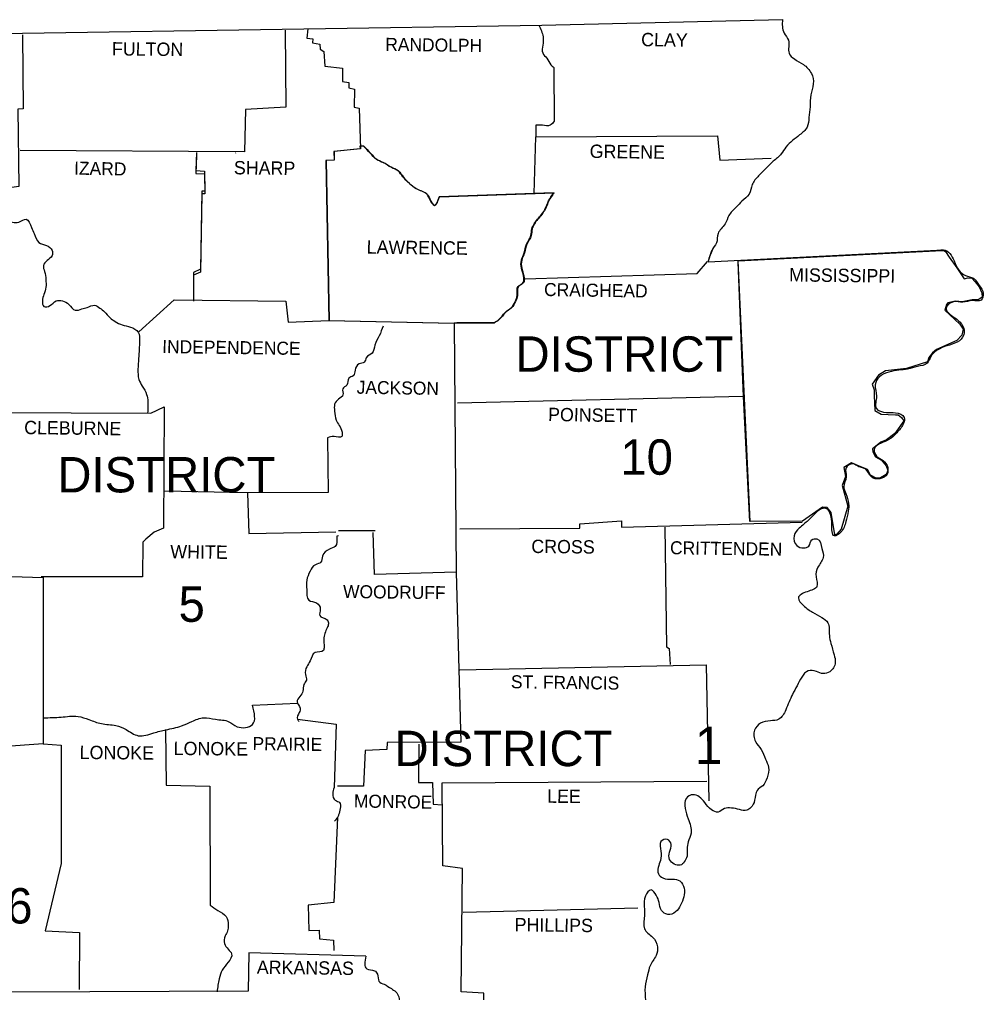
# Model space of a CAD drawing. Extents: x -42408 to 34530, y -43140 to 20491.
# Drawn here: x 3107 to 4663, y -8719 to -7149 of the extents above; entities that cross this region are included whole.
import ezdxf

# ---------------------------------------------------------------- set-up
doc = ezdxf.new("R2010")
doc.units = 0
for name, color, linetype in [('1', 7, 'Continuous'), ('2', 7, 'Continuous'), ('3', 7, 'Continuous'), ('S_MISC_BOUNDARY', 7, 'Continuous')]:
    doc.layers.add(name, color=color, linetype=linetype)

msp = doc.modelspace()

# ---------------------------------------------------------------- linework, layer by layer
at = {"layer": '1'}
for p, q in [((3940.7, -7320.1), (3940.7, -7338.7)), ((3662.3, -7353.7), (3656.7, -7353.9)), ((3968.7, -7429.3), (3784.5, -7435.8)), ((3937.2, -7430.8), (3938.1, -7429.9)), ((3777, -7449.3), (3781.8, -7444.6)), ((4218.6, -7540.4), (4224.6, -7521.9)), ((4220.1, -7534.4), (4226.1, -7519.9)), ((4267, -7538.6), (4596.4, -7522.4)), ((4596.4, -7522.4), (4599.2, -7522.2)), ((4599.2, -7522.2), (4601.6, -7523.9)), ((4601.6, -7523.9), (4607.9, -7533)), ((4607.9, -7533), (4619.9, -7550.3)), ((4286.6, -7959.5), (4267, -7538.6)), ((4619.9, -7550.3), (4632, -7567.6)), ((4632, -7567.6), (4638, -7566)), ((4638, -7566), (4644.1, -7567)), ((4644.1, -7567), (4649.6, -7572.7)), ((4649.6, -7572.7), (4655.9, -7581)), ((4655.9, -7581), (4660.6, -7590.3)), ((4660.7, -7597.3), (4654.5, -7601.7)), ((4660.6, -7590.3), (4660.7, -7597.3)), ((4603.2, -7609.4), (4600.8, -7618.6)), ((4605.3, -7606.6), (4603.2, -7609.4)), ((4618.1, -7603.8), (4605.3, -7606.6)), ((4628.7, -7605), (4618.1, -7603.8)), ((4644.8, -7601.8), (4628.7, -7605)), ((4654.5, -7601.7), (4644.8, -7601.8)), ((4600.8, -7618.6), (4624.9, -7641)), ((4624.9, -7641), (4630.4, -7649.2)), ((4628.3, -7658.9), (4620.1, -7667.1)), ((4630.4, -7649.2), (4628.3, -7658.9)), ((4620.1, -7667.1), (4587.4, -7681.6)), ((4581, -7687), (4575.1, -7694.7)), ((4587.4, -7681.6), (4581, -7687)), ((4572.6, -7702), (4538.6, -7712.7)), ((4575.1, -7694.7), (4572.6, -7702)), ((4493.6, -7723.5), (4483.6, -7737.7)), ((4505, -7716.3), (4493.6, -7723.5)), ((4538.6, -7712.7), (4505, -7716.3)), ((4483.6, -7737.7), (4486.7, -7746.8)), ((4486.7, -7746.8), (4486.7, -7756.5)), ((4486.7, -7756.5), (4487.6, -7780.3)), ((4487.6, -7780.3), (4497.7, -7786.4)), ((4497.7, -7786.4), (4509.4, -7786.7)), ((4509.4, -7786.7), (4521.2, -7787.1)), ((4534.3, -7796.8), (4519.9, -7817.2)), ((4521.2, -7787.1), (4525.4, -7787.2)), ((4525.4, -7787.2), (4530.9, -7791.4)), ((4530.9, -7791.4), (4534.3, -7796.8)), ((4519.9, -7817.2), (4506.4, -7827.5)), ((4497.6, -7831.2), (4484.1, -7842.1)), ((4506.4, -7827.5), (4497.6, -7831.2)), ((4484.1, -7842.1), (4484.6, -7847.2)), ((4484.6, -7847.2), (4488.7, -7855)), ((4449.8, -7864.7), (4437.9, -7872.3)), ((4461.2, -7869.4), (4449.8, -7864.7)), ((4488.7, -7855), (4498.6, -7860.5)), ((4498.6, -7860.5), (4506.2, -7869.7)), ((4437.9, -7872.3), (4438.5, -7878.2)), ((4438.5, -7878.2), (4440.3, -7886.7)), ((4476, -7875.4), (4461.2, -7869.4)), ((4480.9, -7884.4), (4476, -7875.4)), ((4508.8, -7876.9), (4505.8, -7883.3)), ((4506.2, -7869.7), (4508.8, -7876.9)), ((4440.3, -7886.7), (4435.2, -7901.2)), ((4489.8, -7889.4), (4480.9, -7884.4)), ((4496.9, -7889.1), (4489.8, -7889.4)), ((4505.8, -7883.3), (4496.9, -7889.1)), ((4435.2, -7901.2), (4444.1, -7934.5)), ((4403.4, -7936.1), (4371.2, -7958.9)), ((4410.6, -7936.6), (4403.4, -7936.1)), ((4417.2, -7944.7), (4410.6, -7936.6)), ((4444.1, -7934.5), (4433.6, -7971.9)), ((4371.2, -7958.9), (4286.6, -7959.5)), ((4423.4, -7981), (4417.2, -7944.7)), ((3621.8, -7974), (3681.4, -7974)), ((4433.6, -7971.9), (4426.2, -7980)), ((4426.2, -7980), (4423.4, -7981))]:
    msp.add_line(p, q, dxfattribs=at)
for points in [[(1592.1, -7172.4), (2401.7, -7172.9), (3112.1, -7171.4), (3950.2, -7158.4), (4338.7, -7149.4)], [(3536.2, -7166.9), (3537.2, -7291.1), (3472.1, -7294.6), (3470.1, -7362.7), (3108.1, -7360.7)], [(3572.6, -7164.3), (3570.7, -7179.4), (3580.7, -7180.9), (3580.2, -7187), (3591.7, -7189.5), (3592.7, -7197.5), (3598.3, -7201), (3599.8, -7225), (3628.3, -7228), (3628.3, -7249.5), (3638.8, -7251), (3638.8, -7259.6), (3647.8, -7262.1), (3647.3, -7291.1), (3655.3, -7292.6), (3657.3, -7358.2), (3614.8, -7362.2), (3615.3, -7376.2), (3602.3, -7376.7), (3606.8, -7635.1), (3808.5, -7639.6), (3812, -8041.1), (3680.4, -8044.6), (3677.9, -7977)], [(3112.1, -7174.4), (3113.1, -7293.6), (3104.6, -7294.1), (3106.1, -7418.8), (3071.1, -7423.8), (3074.1, -7457.3), (3086.1, -7472.8), (3085.1, -7512.4), (3017, -7514.9), (3014.5, -7576), (2952.4, -7578), (2949.4, -7652.1), (2952.9, -7658.1), (2954.4, -7776.2), (3061.5, -7783.3), (3060, -8047.1), (3145.2, -8049.6), (3145.2, -8318), (3078.1, -8323), (3073.1, -8382), (2960.4, -8382.6)], [(3969.8, -7227), (3970.3, -7313.6)], [(3938.1, -7430.4), (3940.7, -7338.7), (3940.7, -7338.7), (4233.6, -7337.2), (4237.6, -7376.2), (4320.2, -7373.2)], [(3656.7, -7353.9), (3656.8, -7358.2), (3614.3, -7362.2), (3614.8, -7376.2), (3601.8, -7376.7), (3606.3, -7635.1), (3808, -7639.6)], [(3393, -7364.2), (3392, -7393.2), (3406, -7394.2), (3406.5, -7426.3), (3401.5, -7426.3), (3399.5, -7552.4), (3388, -7557.4), (3388, -7599.5)], [(3393, -7368.7), (3392, -7397.7), (3406, -7398.7), (3406.5, -7430.8), (3401.5, -7430.8), (3399.5, -7556.9), (3388, -7562), (3388, -7604)], [(3455.6, -7365.2), (3456.1, -7364.7)], [(3785, -7435.8), (3970.8, -7429.3)], [(3968.8, -7429.8), (3968.7, -7429.3)], [(4218.6, -7540.4), (4598.6, -7520.9)], [(3923.2, -7568), (4201.1, -7559), (4217.6, -7539.9)], [(4266.6, -7540.9), (4275.2, -7757.7), (4285.2, -7959.5)], [(3299.9, -7653.1), (3356.9, -7601.5), (3537.2, -7604), (3540.7, -7637.6), (3606.3, -7635.1)], [(3808, -7639.6), (3812.5, -7638.6), (3873.6, -7638.6)], [(3874.1, -7638.6), (3813, -7638.6), (3808.5, -7639.6)], [(4275.2, -7757.7), (3814, -7768.2)], [(3061.5, -7783.3), (3318.9, -7784.8), (3340.9, -7774.2), (3339.4, -7970), (3324.4, -7976.5), (3310.9, -7988), (3306.4, -7992.5), (3305.9, -8048.6), (3142.1, -8048.6)], [(3604.3, -7824.3), (3605.3, -7912.4), (3475.1, -7912.9), (3341.4, -7910.4)], [(3475.1, -7912.9), (3477.1, -7978.5), (3617.8, -7976)], [(3818, -7971), (4011.3, -7970), (4011.8, -7963), (4078.9, -7958), (4078.9, -7968.5), (4370.3, -7960.5)], [(4149, -7968.5), (4151.5, -8161.3), (4156, -8164.3), (4157.5, -8190.3)], [(3621.8, -7982.5), (3619.3, -7983)], [(3812, -8041.1), (3819.6, -8315.5), (3700.4, -8316), (3699.9, -8327), (3665.3, -8329), (3662.3, -8386.1), (3620.3, -8386.1)], [(3818, -8198.8), (4215.6, -8190.8)], [(4215.6, -8190.8), (4219.6, -8410.1)], [(3483.1, -8255.9), (3555.7, -8252.4)], [(3555.7, -8278.4), (3618.3, -8286.4), (3614.8, -8388.6)], [(3342.9, -8294.9), (3343.9, -8384.6), (3414.5, -8386.1), (3415, -8578.3)], [(3145.2, -8318), (3174.2, -8320), (3174.7, -8511.2), (3148.7, -8619.9), (3204.2, -8622.4), (3203.7, -8714.5)], [(3751.5, -8318.5), (3751, -8380.5), (3774, -8380.5), (3775, -8415.1), (3789.5, -8416.6)], [(3818, -8824.6), (3857.1, -8822.1), (3856.6, -8720.5), (3820.1, -8718), (3822.1, -8519.2), (3790.5, -8514.7), (3789.5, -8381), (4216.6, -8378)], [(3620.3, -8436.6), (3614.3, -8573.8), (3573.2, -8578.3), (3574.2, -8618.9), (3590.7, -8618.4), (3591.2, -8632.4), (3613.8, -8634.9), (3614.3, -8651.4)], [(3823.1, -8589.8), (4105.4, -8582.8)], [(3666.3, -8660.4), (3477.1, -8655.4), (3476.1, -8717), (3093.1, -8718.5)]]:
    msp.add_lwpolyline(points, dxfattribs=at)
for points in [[(3945.4, -7158.5), (3952.2, -7177.4), (3951.7, -7191), (3951.7, -7203.5), (3958.2, -7212), (3964.7, -7222.5), (3969.8, -7227)], [(4338.7, -7149.4), (4341.2, -7171.4), (4348.3, -7183), (4349.3, -7204), (4357.8, -7213), (4372.3, -7222), (4385.3, -7236.5), (4388.3, -7253.5), (4384.3, -7271.1), (4383.3, -7290.6), (4381.3, -7307.6), (4378.3, -7323.1), (4366.3, -7335.7), (4354.8, -7344.7), (4344.3, -7355.2), (4336.7, -7366.2), (4323.7, -7378.2), (4310.7, -7390.7), (4300.2, -7401.7), (4289.7, -7415.8), (4284.7, -7431.3), (4273.2, -7442.3), (4264.1, -7452.3), (4252.1, -7465.8), (4246.1, -7479.3), (4234.6, -7494.9), (4232.1, -7509.9), (4224.6, -7521.9), (4224.1, -7523.9)], [(3970.3, -7313.6), (3963.7, -7320.1), (3951.2, -7320.1), (3940.7, -7320.1)], [(3784.5, -7435.8), (3776.5, -7449.3), (3769, -7438.8), (3763.5, -7430.3), (3747, -7422.3), (3736.4, -7413.8), (3725.9, -7403.2), (3718.4, -7393.7), (3706.9, -7387.7), (3693.9, -7380.2), (3682.9, -7374.7), (3673.4, -7365.2), (3662.3, -7353.7)], [(3662.8, -7353.7), (3673.9, -7365.2), (3683.4, -7374.7), (3694.4, -7380.2), (3707.4, -7387.7), (3718.9, -7393.7), (3726.4, -7403.2), (3736.9, -7413.8), (3747.5, -7422.3), (3764, -7430.3), (3769.5, -7438.8), (3777, -7449.3), (3785, -7435.8)], [(3873.6, -7638.6), (3881.1, -7633.6), (3891.1, -7622), (3900.7, -7614.5), (3907.2, -7604.5), (3910.2, -7594.5), (3912.2, -7580), (3919.7, -7574.5), (3920.7, -7563), (3917.2, -7550.4), (3917.2, -7537.9), (3921.7, -7525.9), (3925.7, -7511.9), (3932.7, -7497.9), (3934.2, -7487.4), (3943.2, -7471.8), (3955.2, -7455.8), (3961.2, -7441.8), (3968.8, -7429.8)], [(3969.3, -7429.8), (3961.7, -7441.8), (3955.7, -7455.8), (3943.7, -7471.8), (3934.7, -7487.4), (3933.2, -7497.9), (3926.2, -7511.9), (3922.2, -7525.9), (3917.7, -7537.9), (3917.7, -7550.4), (3921.2, -7563), (3920.2, -7574.5), (3912.7, -7580), (3910.7, -7594.5), (3907.7, -7604.5), (3901.2, -7614.5), (3891.6, -7622), (3881.6, -7633.6), (3874.1, -7638.6)], [(3086.1, -7472.8), (3106.1, -7476.3), (3118.1, -7471.8), (3126.6, -7484.9), (3131.1, -7494.9), (3138.6, -7509.4), (3150.7, -7513.9), (3159.7, -7521.9), (3159.7, -7530.4), (3151.7, -7538.4), (3145.7, -7546.4), (3147.7, -7555.9), (3149.7, -7569), (3149.7, -7581.5), (3146.7, -7593), (3144.2, -7603.5), (3146.7, -7612.5), (3156.2, -7611), (3166.2, -7603.5), (3176.7, -7603.5), (3186.7, -7609), (3197.2, -7618.5), (3207.7, -7616.5), (3216.2, -7614), (3228.3, -7610.5), (3236.8, -7615), (3244.3, -7621), (3253.3, -7630.5), (3261.8, -7636.6), (3272.8, -7642.1), (3286.3, -7645.6), (3298.9, -7654.1), (3300.9, -7668.6), (3300.4, -7681.1), (3299.4, -7696.6), (3298.4, -7713.7), (3299.9, -7730.2), (3305.4, -7741.2), (3312.4, -7754.2), (3314.4, -7766.2), (3313.9, -7785.3)], [(4593.1, -7521.4), (4598.6, -7520.9), (4615.6, -7538.9), (4623.1, -7553.9), (4634.1, -7562.5), (4646.7, -7567), (4656.2, -7578.5), (4662.7, -7591), (4659.2, -7602), (4645.2, -7603), (4629.6, -7605.5), (4614.6, -7605), (4602.6, -7615), (4613.6, -7628.5), (4628.1, -7641.1), (4632.1, -7654.6), (4624.1, -7667.6), (4608.1, -7674.6), (4592.6, -7680.6), (4578.6, -7692.6), (4572.1, -7704.1), (4556.5, -7709.2), (4540.5, -7713.7), (4526.5, -7715.2), (4510.5, -7718.2), (4495, -7725.7), (4488.4, -7738.7), (4490.4, -7757.2), (4489.9, -7776.7), (4506.5, -7783.3), (4521, -7783.8), (4535, -7791.3), (4533.5, -7802.3), (4523, -7816.3), (4510.5, -7827.3), (4498, -7832.8), (4486.4, -7843.3), (4490.4, -7853.8), (4501, -7860.9), (4508.5, -7872.4), (4507.5, -7882.9), (4495.5, -7890.4), (4482.4, -7887.4), (4472.9, -7874.9), (4461.9, -7870.9), (4452.4, -7866.4), (4441.4, -7872.9), (4441.4, -7887.4), (4437.4, -7902.9), (4440.9, -7914.4), (4445.4, -7930.4), (4444.9, -7942.5), (4440.9, -7959.5), (4432.4, -7977), (4422.4, -7982.5), (4418.3, -7963.5), (4416.3, -7948), (4410.3, -7939), (4402.3, -7938.5), (4391.8, -7946), (4380.3, -7957.5), (4365.8, -7970), (4357.3, -7982.5), (4361.8, -7998), (4372.8, -8002), (4381.3, -7999), (4385.8, -7989), (4394.3, -7987.5), (4402.3, -8003)], [(3693.9, -7644.1), (3687.9, -7659.6), (3680.9, -7674.6), (3676.4, -7687.6), (3666.8, -7695.1), (3663.8, -7702.1), (3655.3, -7705.1), (3648.8, -7715.2), (3645.8, -7724.2), (3638.8, -7728.2), (3635.3, -7739.2), (3628.8, -7745.2), (3629.3, -7755.2), (3621.8, -7762.2), (3615.8, -7770.2), (3615.8, -7781.2), (3618.3, -7795.8), (3623.3, -7804.3), (3627.8, -7815.3), (3627.3, -7822.3), (3614.8, -7822.3), (3604.3, -7824.3)], [(3619.3, -7983), (3616.8, -7999.5), (3607.3, -8004), (3596.3, -8015.1), (3593.7, -8025.1), (3584.7, -8029.1), (3576.2, -8039.6), (3570.7, -8054.1), (3570.7, -8069.1), (3574.2, -8086.2), (3586.7, -8090.7), (3592.7, -8100.7), (3591.7, -8111.2), (3603.8, -8118.2), (3605.8, -8124.2), (3603.8, -8130.7), (3598.3, -8149.2), (3598.8, -8161.8), (3597.8, -8167.3), (3584.2, -8170.8), (3576.2, -8184.3), (3570.7, -8193.8), (3568.7, -8206.3), (3570.2, -8215.3), (3566.2, -8222.3), (3564.7, -8232.9), (3559.7, -8241.9), (3555.2, -8250.4), (3560.2, -8260.4), (3558.7, -8267.4), (3555.7, -8278.4), (3558.2, -8281.9)], [(4402.3, -8003), (4404.3, -8017.6), (4395.8, -8033.1), (4392.8, -8048.6), (4394.3, -8064.1), (4378.3, -8072.6), (4364.3, -8082.7), (4372.3, -8094.7), (4387.3, -8105.7), (4402.3, -8114.2), (4411.8, -8122.7), (4414.3, -8143.2), (4416.8, -8156.2), (4421.9, -8174.3), (4423.9, -8186.8), (4414.8, -8201.8), (4404.3, -8204.8), (4393.3, -8201.3), (4380.3, -8200.3), (4369.8, -8210.3), (4362.3, -8224.3), (4354.8, -8238.4), (4349.3, -8250.4), (4343.8, -8263.4), (4332.7, -8278.4), (4319.2, -8280.9), (4303.2, -8284.9), (4293.7, -8295.9), (4295.2, -8314.5), (4304.2, -8327), (4311.2, -8342.5), (4316.2, -8356), (4313.7, -8373), (4306.7, -8385.6), (4297.7, -8393.1), (4293.7, -8409.1), (4287.2, -8421.1), (4281.2, -8425.1), (4269.2, -8424.1), (4256.1, -8421.6), (4245.1, -8422.6), (4234.6, -8428.1), (4224.1, -8424.6), (4213.1, -8412.6), (4204.1, -8403.6), (4194.1, -8400.1), (4183.5, -8405.6), (4181.5, -8422.1), (4186.5, -8439.1), (4191, -8462.2), (4186.5, -8476.2), (4185, -8499.2)], [(3146.2, -8275.9), (3174.2, -8274.9), (3201.7, -8273.9), (3219.3, -8278.9), (3239.3, -8285.4), (3262.8, -8288.4), (3279.3, -8294.9), (3298.9, -8304.9), (3323.9, -8300.4), (3343.4, -8295.4), (3368.9, -8288.9), (3385.5, -8281.9), (3404.5, -8275.9), (3423.5, -8278.4), (3445.1, -8282.4), (3458.6, -8290.4), (3483.1, -8286.9), (3483.1, -8255.9)], [(3614.8, -8388.6), (3612.8, -8398.6), (3616.8, -8409.1), (3623.8, -8412.6), (3624.8, -8422.6), (3622.3, -8432.6), (3620.3, -8436.6), (3615.8, -8442.6)], [(4185, -8499.2), (4173.5, -8513.7), (4156.5, -8504.7), (4156.5, -8492.7), (4159, -8480.2), (4153, -8472.2), (4142.5, -8475.7), (4142.5, -8491.2), (4141.5, -8506.2), (4138.5, -8527.7), (4145.5, -8534.3), (4161.5, -8536.3), (4173, -8539.3), (4180, -8550.8), (4179.5, -8564.8), (4174, -8578.3), (4166, -8589.3), (4153.5, -8593.3), (4143.5, -8586.8), (4139.5, -8573.8), (4135, -8562.3), (4126.5, -8553.8), (4117.4, -8563.3), (4115.4, -8580.8), (4115.9, -8595.8), (4115.9, -8616.4), (4129, -8629.9), (4137, -8645.4), (4134.5, -8659.4), (4125, -8675.9), (4121, -8690.5), (4116.9, -8710), (4117.4, -8731.5), (4113.9, -8752.5), (4106.9, -8766.6), (4093.9, -8778.1), (4085.4, -8785.6), (4078.4, -8793.1), (4074.9, -8808.1), (4072.4, -8818.6), (4062.9, -8831.1), (4055.4, -8832.2), (4049.4, -8827.1), (4047.4, -8818.6), (4047.4, -8810.1), (4043.3, -8801.6), (4030.8, -8798.1), (4020.8, -8798.6), (4016.3, -8805.6), (4022.8, -8825.1), (4025.3, -8837.7), (4021.8, -8854.7), (4023.8, -8856.7), (4005.8, -8866.2), (3991.3, -8867.7), (3979.3, -8871.2), (3967.7, -8878.7), (3962.2, -8889.7), (3954.2, -8898.7), (3947.2, -8907.3), (3937.7, -8911.3), (3927.2, -8909.3), (3913.2, -8907.8), (3905.2, -8917.8), (3907.7, -8932.3), (3917.2, -8940.8), (3931.2, -8944.8), (3945.7, -8943.8), (3959.7, -8942.3), (3972.8, -8949.3), (3970.3, -8962.8), (3957.7, -8969.3), (3939.2, -8971.3), (3924.2, -8969.8), (3906.2, -8973.8), (3897.2, -8985.4), (3902.2, -9002.9), (3921.7, -9009.9), (3930.7, -9026.4), (3931.2, -9041.9), (3924.7, -9062.5), (3915.7, -9072), (3898.2, -9076), (3884.6, -9078.5), (3882.6, -9101.5), (3876.6, -9113), (3866.1, -9116.5), (3851.1, -9109), (3842.1, -9105.5), (3831.1, -9100.5), (3817, -9092), (3806.5, -9093.5), (3809.5, -9115.5), (3810.5, -9116.5), (3822.6, -9133.1), (3834.6, -9146.1), (3840.1, -9161.6)], [(3415, -8578.3), (3427.5, -8586.8), (3440.5, -8596.8), (3444.1, -8610.4), (3443, -8619.9), (3439, -8627.9), (3438, -8640.4), (3444.1, -8649.4), (3449.6, -8656.9), (3444.1, -8670.4), (3434.5, -8683), (3429.5, -8697), (3426, -8718)], [(3666.3, -8660.4), (3667.8, -8680.9), (3679.9, -8684), (3684.9, -8689.5), (3687.4, -8701), (3695.9, -8706), (3707.4, -8713), (3714.4, -8718), (3719.4, -8726), (3722.4, -8739), (3730.4, -8747.5), (3741.4, -8751.5), (3749.5, -8761.1), (3754.5, -8774.6), (3762.5, -8780.6), (3770.5, -8791.1), (3774.5, -8795.6), (3781.5, -8807.6), (3788.5, -8813.6), (3793.5, -8817.1), (3801.5, -8819.6), (3811.5, -8826.1), (3818, -8836.2), (3818, -8843.7), (3815.5, -8855.2), (3813.5, -8867.2), (3812.5, -8880.7), (3811.5, -8892.7), (3816, -8902.7), (3813.5, -8917.8), (3808.5, -8925.8), (3808, -8936.8), (3806.5, -8953.3), (3804.5, -8962.8), (3800, -8978.3), (3793.5, -8986.4)]]:
    msp.add_spline(points, degree=3, dxfattribs=at)
at = {"layer": 'S_MISC_BOUNDARY'}
msp.add_line((3662.8, -7353.7), (3657.2, -7353.9), dxfattribs=at)

# ---------------------------------------------------------------- texts
at = {"layer": '1'}
msp.add_text('1', height=60.1, dxfattribs=at).set_placement((4197.1, -8350.5))
at = {"layer": '2'}
for s, height, rotation, p in [('CLAY', 21.52, 359.2258, (4110.4, -7192.5)), ('FULTON', 21.52, 359.4996, (3256.3, -7207.5)), ('RANDOLPH', 21.03, 359.2583, (3697.4, -7200)), ('GREENE', 21.53, 359.2361, (4027.3, -7372.7)), ('SHARP', 21.52, 359.3905, (3453.1, -7399.2)), ('IZARD', 21.02, 358.9258, (3195.2, -7399.7)), ('LAWRENCE', 21.53, 359.2678, (3667.4, -7527.1)), ('MISSISSIPPI', 21.524, 359.3097, (4349.3, -7572)), ('CRAIGHEAD', 21.03, 359.1159, (3953.7, -7595.5)), ('INDEPENDENCE', 21.022, 359.2187, (3337.4, -7687.6)), ('JACKSON', 21.02, 359.1352, (3651.3, -7753.2)), ('POINSETT', 21.52, 359.1987, (3960.2, -7797.3)), ('CLEBURNE', 21.52, 359.2535, (3114.6, -7818.3)), ('CROSS', 21.52, 359.3839, (3933.2, -8010.1)), ('WHITE', 21.53, 359.3139, (3350.4, -8018.6)), ('CRITTENDEN', 21.03, 359.213, (4157, -8012.1)), ('WOODRUFF', 21.02, 359.2748, (3629.3, -8082.7)), ('ST. FRANCIS', 21.022, 359.2216, (3900.2, -8228.3)), ('LONOKE', 21.53, 359.4974, (3355.9, -8336)), ('PRAIRIE', 21.03, 359.2116, (3483.1, -8328)), ('LONOKE', 21.53, 359.4974, (3204.2, -8342.5)), ('LEE', 21.53, 359.4327, (3958.7, -8413.1)), ('MONROE', 21.02, 359.0331, (3646.8, -8420.6)), ('PHILLIPS', 21.52, 359.3179, (3906.2, -8620.4)), ('ARKANSAS', 21.52, 359.2678, (3490.1, -8689))]:
    msp.add_text(s, height=height, rotation=rotation, dxfattribs=at).set_placement(p)
at = {"layer": '3'}
for s, height, p in [('DISTRICT', 57.08, (3907.7, -7717.7)), ('10', 57.08, (4076.9, -7883.9)), ('DISTRICT', 57.08, (3168.2, -7912.4)), ('5', 57.1, (3363.9, -8121.2)), ('DISTRICT', 57.08, (3712.4, -8354)), ('DISTRICT 6', 57.08, (2712.6, -8607.9))]:
    msp.add_text(s, height=height, dxfattribs=at).set_placement(p)

doc.saveas('drawing.dxf')
